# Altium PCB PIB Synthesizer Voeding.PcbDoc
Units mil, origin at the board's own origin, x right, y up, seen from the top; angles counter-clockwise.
Board outline 7800 x 2080 mil, 2 copper layers (Top Layer, Bottom Layer); 39 components, 26 nets, 116 pads, 17 vias.
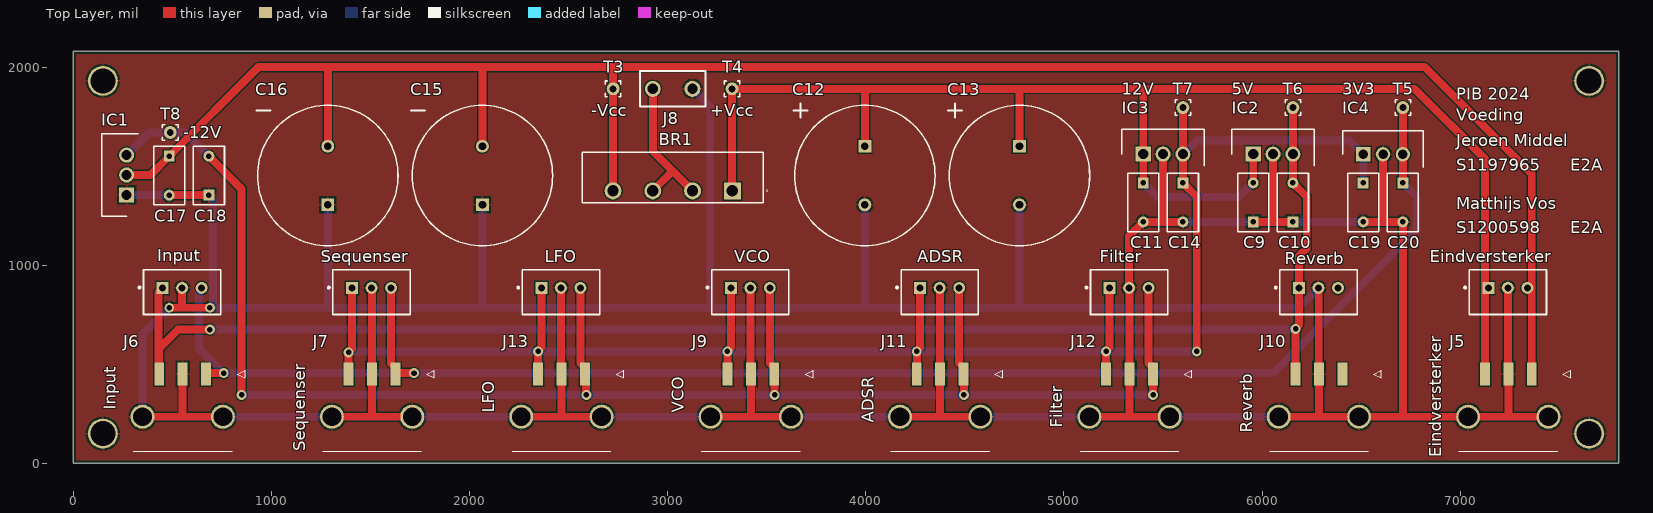
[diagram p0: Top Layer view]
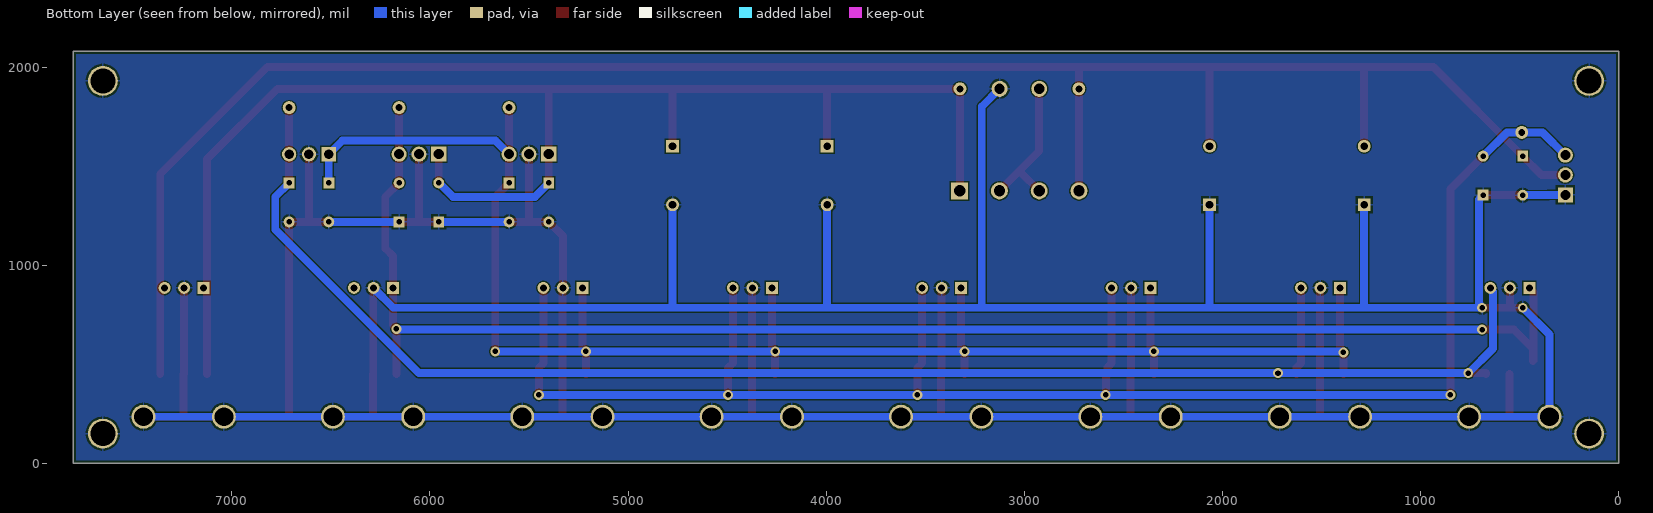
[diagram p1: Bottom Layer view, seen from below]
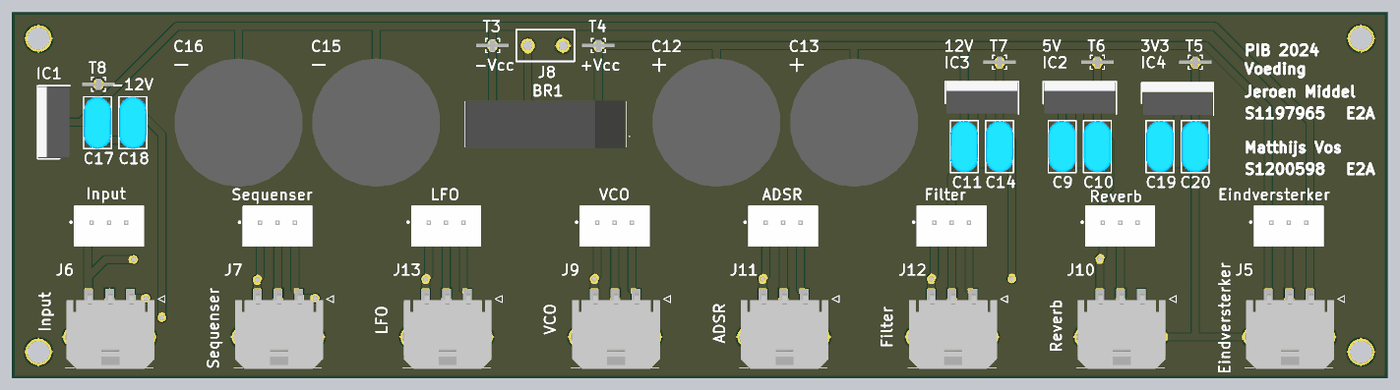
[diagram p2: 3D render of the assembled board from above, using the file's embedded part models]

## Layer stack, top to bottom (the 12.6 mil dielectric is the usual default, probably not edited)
Top Solder: solder mask 0.4, Solder Resist, Dk 3.5
Top Layer: signal copper 1.4
Dielectric 1: dielectric 12.6, FR-4, Dk 4.8
Bottom Layer: signal copper 1.4
Bottom Solder: solder mask 0.4, Solder Resist, Dk 3.5

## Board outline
0,0 7800,0 7800,2080 0,2080

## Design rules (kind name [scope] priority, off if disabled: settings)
BoardOutlineClearance "BoardOutlineClearance AISLER" [All] p1: gap=11.81 ignorepadtopadclearanceinfootprint=FALSE
Clearance "Clearance AISLER Simple" [All] p1: gap=5.91 ignorepadtopadclearanceinfootprint=FALSE except(0: Arc-Text Track-Text SMDPad-Text THPad-Text Via-Text Fill-Text Poly-Text Region-Text Text-Text Text-Hole; 7.87: Fill-Fill Fill-Poly Fill-Region Poly-Poly Poly-Region Region-Region; 9.84: Arc-Hole Track-Hole SMDPad-Hole THPad-Hole Via-Hole Fill-Hole Poly-Hole Region-Hole)
Height [All] p1: minheight=0 maxheight=3000 prefheight=500
HoleSize [All] p1: absolutevalues=TRUE maxlimit=220 minlimit=1 maxpercent=80.000 minpercent=20.000
HoleSize "HoleSize NPTH AISLER Simple" [PadIsPlated = 'False'] p2: absolutevalues=TRUE maxlimit=228.35 minlimit=11.81 maxpercent=80.000 minpercent=20.000
HoleSize "HoleSize PTH AISLER Simple" [All] p3: absolutevalues=TRUE maxlimit=222.44 minlimit=11.81 maxpercent=80.000 minpercent=20.000
HoleToHoleClearance "HoleToHoleClearance NPTH-NPTH AISLER" [PadIsPlated = 'False' vs PadIsPlated = 'False'] p2: gap=11.81 allowstackedmicrovias=FALSE // 0.25 + (0.05/2 + 0.05/2)
HoleToHoleClearance "HoleToHoleClearance NPTH-PTH AISLER" [PadIsPlated = 'False' vs PadIsPlated = 'True'] p3: gap=13.78 allowstackedmicrovias=FALSE // 0.25 + (0.05/2 + 0.15/2)
HoleToHoleClearance "HoleToHoleClearance Rest AISLER" [All] p4: gap=15.75 allowstackedmicrovias=FALSE // 0.25 + (0.15/2 + 0.15/2)
MinimumAnnularRing "MinimumAnnularRing AISLER" [IsVia] p1: minimumring=7.87
MinimumAnnularRing [All] p2: minimumring=12
MinimumSolderMaskSliver "MinimumSolderMaskSliver AISLER" [All] p2: minsoldermaskwidth=4.53 // AISLER enlarges all Solder Mask Openings by 20um by default, final Sliver is thus 0.075mm
PlaneClearance "PlaneClearance AISLER Simple" [All] p2: clearance=7.87
PolygonConnect [All] p1: connectstyle=Relief reliefconductorwidth=10 reliefentries=4 polygonreliefangle="90 Angle" airgapwidth=10
RoutingVias [All] p1: holewidth=28 width=50 viastyle="Through Hole" minholewidth=28 minwidth=50 maxholewidth=28 maxwidth=50
RoutingVias "RoutingVias AISLER Simple" [All] p2: holewidth=29.53 width=45.28 viastyle="Through Hole" minholewidth=11.81 minwidth=27.56 maxholewidth=39.37 maxwidth=55.12 // only minimum size relevant
SilkToSolderMaskClearance "SilkToSolderMaskClearance AISLER" [IsPad] p1: minsilkscreentomaskgap=5 clearancetoexposedcopper=TRUE
SolderMaskExpansion [All] p1: expansion=4 istentingtop=FALSE
Width [All] p1: maxlimit=40 minlimit=40 preferedwidth=40 minimp=50.000000 maximp=50.000000 favimp=50.000000
Width "Width AISLER Simple" [All] p2: maxlimit=59.06 minlimit=7.87 preferedwidth=19.68 // only min is relevant
27 further rules are at their usual default settings.

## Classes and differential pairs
component class "PIB Synthesizer Eindversterker": U1A U1B X1
component class "PIB Synthesizer Voeding": 5V 12V BR1 C9 C10 C12 C13 C14 C15 C16 C17 C18 C19 C20 IC1 IC4 J5 J6 J7 J9 J10 J11 J12 J13 "T3 -" "T4 +" T5 T6 T7 T8

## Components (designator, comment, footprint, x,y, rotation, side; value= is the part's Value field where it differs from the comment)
ADSR "Comment" FP-B3B-XH-A_LF_SN-MFG 4372.86,864.33 r0 top
BR1 "KBU8B-E4_51" KBU8BE451 3326.57,1375 r0 top
C9 "220nF" FP-RDE4K1-MFG 5955,1316.57 r90 top
C10 "100nF" FP-RDE4K1-MFG 6155,1316.57 r90 top
C11 "220nF" FP-RDE4K1-MFG 5400,1316.57 r270 top
C12 "4700µF" CAPPRD750W82D1800H3750 3995,1600 r270 top
C13 "4700µF" CAPPRD750W82D1800H3750 4775,1600 r270 top
C14 "100nF" FP-RDE4K1-MFG 5600,1316.57 r270 top
C15 "4700µF" CAPPRD750W82D1800H3750 2065,1304.72 r90 top
C16 "4700µF" CAPPRD750W82D1800H3750 1285,1304.72 r90 top
C17 "220nF" FP-RDE4K1-MFG 485,1451.57 r270 top
C18 "100nF" FP-RDE4K1-MFG 685,1451.57 r90 top
C19 "330uF" FP-RDE4K1-MFG 6510,1316.57 r270 top
C20 "100nF" FP-RDE4K1-MFG 6710,1316.57 r270 top
Eindversterker "Comment" FP-B3B-XH-A_LF_SN-MFG 7240,864.33 r0 top
Filter "Comment" FP-B3B-XH-A_LF_SN-MFG 5328.57,864.33 r0 top
IC1 "LM7912CT" TO254P470X1028X1955-3P 270,1355 r90 top (schematic designator U2)
IC2 "5V" TO254P470X1028X1955-3P 5955,1560 r0 top
IC3 "12V" TO254P470X1028X1955-3P 5400,1560 r0 top
IC4 "3V3" TO254P470X1016X1965-3P 6510,1560 r0 top
Input "Comment" FP-B3B-XH-A_LF_SN-MFG 550,864.33 r0 top
J5 "Eindversterker" 43650-03YY_091011 7242.24,450.35 r0 top
J6 "Input" 43650-03YY_091011 552.76,450.35 r0 top
J7 "Sequenser" 43650-03YY_091011 1508.4,450.35 r0 top
J9 "VCO" 43650-03YY_091011 3419.68,450.35 r0 top
J10 "Reverb" 43650-03YY_091011 6286.6,450.35 r0 top
J11 "ADSR" 43650-03YY_091011 4375.32,450.35 r0 top
J12 "Filter" 43650-03YY_091011 5330.96,450.35 r0 top
J13 "LFO" 43650-03YY_091011 2464.04,450.35 r0 top
LFO "Comment" FP-B3B-XH-A_LF_SN-MFG 2461.43,864.33 r0 top
Reverb "Comment" FP-B3B-XH-A_LF_SN-MFG 6284.29,864.33 r0 top
Sequenser "Comment" FP-B3B-XH-A_LF_SN-MFG 1505.71,864.33 r0 top
T3 "Testpoint -Vcc" SAMTEC_MTMM-101-X-X-S-X 2725,1890 r90 top
T4 "Testpoint +Vcc" SAMTEC_MTMM-101-X-X-S-X 3325,1890 r90 top
T5 "Testpoint +3v3" SAMTEC_MTMM-101-X-X-S-X 6710,1795 r90 top
T6 "Testpoint +5v" SAMTEC_MTMM-101-X-X-S-X 6155,1795 r90 top
T7 "Testpoint +12v" SAMTEC_MTMM-101-X-X-S-X 5600,1795 r90 top
T8 "Testpoint -12v" SAMTEC_MTMM-101-X-X-S-X 490,1670 r90 top
VCO "Comment" FP-B3B-XH-A_LF_SN-MFG 3417.14,864.33 r0 top

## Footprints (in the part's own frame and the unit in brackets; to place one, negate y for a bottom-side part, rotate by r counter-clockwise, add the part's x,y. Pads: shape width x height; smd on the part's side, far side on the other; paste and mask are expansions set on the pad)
43650-03YY_091011 [mm]
  rect 1.27x2.92 smd: 1(3,0) 2(0,0) 3(-3,0)
  round 3.062 hole 2.41: 4(5.15,-5.47) 5(-5.15,-5.47)
  silkscreen extent -6.32,-9.9 8,0.5, body extent -6.17,-10.06 6.47,0.68, height 5.71
CAPPRD750W82D1800H3750 [mm]
  rect 1.652x1.652 hole 1: 1(0,0)
  round 1.652 hole 1: 2(7.5,0)
  silkscreen extent -5.25,-9 12.75,9, body extent -5.5,-9.23 13,9.23, height 37.5
FP-B3B-XH-A_LF_SN-MFG [mm]
  rect 1.527x1.527 hole 0.9 paste-2539.97 mask+0: 1(-2.5,0.525)
  round 1.527 hole 0.9 paste-2539.97 mask+0: 2(0,0.525) 3(2.5,0.525)
  silkscreen extent -5.6,-2.88 4.95,2.88, body extent -5.05,-2.98 5.05,2.98, height 0.25
FP-RDE4K1-MFG [mm]
  rect 1.403x1.403 hole 0.7 paste-2539.97 mask+0: 1(-2.5,0)
  round 1.403 hole 0.7 paste-2539.97 mask+0: 2(2.5,0)
  silkscreen extent -3.75,-2 3.75,2, body extent -3.85,-2.1 3.85,2.1, height 0.25
KBU8BE451 [mm]
  rect 2.175x2.175 hole 1.45: 1(0,0)
  round 2.175 hole 1.45: 2(-5.1,0) 3(-10.2,0) 4(-15.3,0)
  silkscreen extent -19.25,-1.53 4.5,4.95, body extent -19.25,-1.71 3.95,5.14, height 20.51
SAMTEC_MTMM-101-X-X-S-X [mm]
  round 1.652 hole 0.89: 01(0,0)
  silkscreen extent -1,-1 1,1
TO254P470X1016X1965-3P [mm]
  rect 1.83x1.83 hole 1.22: 1(0,0)
  round 1.83 hole 1.22: 2(2.54,0) 3(5.08,0)
  silkscreen extent -2.64,-1.68 7.72,3.03, body extent -2.54,-1.61 7.62,2.96, height 21.39
TO254P470X1028X1955-3P [mm]
  rect 1.935x1.935 hole 1.29: 1(0,0)
  round 1.935 hole 1.29: 2(2.54,0) 3(5.08,0)
  silkscreen extent -2.73,-1.5 7.81,3.2, body extent -2.54,-1.43 7.62,3.14, height 19.38

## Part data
BR1: "Bridge Rectifier", Arrow Part Number=KBU8B-E4/51, Manufacturer_Name=Vishay, Mouser Part Number=625-KBU8B-E4
C9 C10 C11 C14 C17 C18 C19 C20: library part CMP-06035-043861-1, "Ceramic Capacitor 47nF ±10% 1kV X7R Radial", Case/Package=Radial, Dielectric=X7R, Max Operating Temperature=125°C, Min Operating Temperature=-55°C, Package Quantity=500, Resistor Type=Ceramic, Tolerance=10%, Voltage Rating=1kV
C12 C13 C15 C16: library part 860020581026, "Capacitor Polarised", Manufacturer_Name="Wurth Elektronik", Mouser Part Number=710-860020581026
IC1: "Undefined or Miscellaneous", Manufacturer_Name="Texas Instruments", Mouser Part Number=926-LM7912CT
IC2: library part LM7805CT, "Integrated Circuit", Manufacturer_Name="Texas Instruments", Mouser Part Number=926-LM7805CT
IC3: library part LM7812CT, "Integrated Circuit", Manufacturer_Name="Texas Instruments", Mouser Part Number=926-LM7812CT
IC4: library part UA78M33CKCSE3, "Integrated Circuit", Manufacturer_Name="Texas Instruments", Mouser Part Number=595-UA78M33CKCSE3
J5 J6 J7 J9 J10 J11 J12 J13: library part 43650-0310, "Connector", Manufacturer_Name=Molex, Mouser Part Number=538-43650-0310
T3 T4 T5 T6 T7 T8: library part MTMM-101-X-X-S-X, "Connector Header Through Hole 1 position", Package=None

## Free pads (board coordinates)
  round 150.98 hole 125.98: 4(150,150) 4(150,1930) 4(7650,150) 4(7650,1930)
  round 80.93 hole 51.18: 5(2925,1890) 6(3125,1890)

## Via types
v1: diameter 50, hole 28, Top Layer to Bottom Layer, 17 vias

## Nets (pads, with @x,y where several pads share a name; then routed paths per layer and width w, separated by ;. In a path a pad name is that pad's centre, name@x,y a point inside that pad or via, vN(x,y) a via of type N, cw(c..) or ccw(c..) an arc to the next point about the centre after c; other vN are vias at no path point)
+3v3: C20.1 IC4.3 Input.3 J6.1 J7.1 Sequenser.3 T5.01 | length 8078.2
  Top Layer w40: J6.1 J6.1@671.04,450.18 ; J6.1@671.04,455.18 v1@759.82,455.18 ; v1@759.82,450.18 v1@760,450 ; Sequenser.3 1604.14,505.2 1626.51,482.83 J7.1 ; J7.1@1626.68,455.18 v1@1719.82,455.18 ; v1@1719.82,450.18 v1@1720,450 ; C20.1 IC4.3 T5.01
  Bottom Layer w40: Input.3 648.43,880.91 635,867.48 635,580 v1(760,455) v1(1720,455) 6055,455 6780,1180 6780,1345 C20.1
+5: C10.2 IC2.3 Input.1 J6.3 J10.3 Reverb.1 T6.01 | length 7617.4
  Top Layer w40: Input.1 430,863.43 430,579.65 430,519.65 434.65,515 434.65,579.65 530,675 v1(690,675) ; T6.01 IC2.3 C10.2 6225,1345 6225,1085 6185.86,1045.86 Reverb.1 6185.86,698.57 6168.49,681.2 v1(6168.49,678.49) J10.3
  Bottom Layer w40: v1(690,675) v1@6170,675
+12: ADSR.1 C14.1 C19.1 Filter.1 IC3.3 IC4.1 J7.3 J9.3 J11.3 J12.3 J13.3 LFO.1 Sequenser.1 T7.01 VCO.1 | length 8859.3
  Top Layer w40: v1(1390,560) 1390,562.71 1407.29,579.99 Sequenser.1 ; J7.3 v1@1390.29,560 ; J13.3 v1(2345.93,565) 2345.93,567.71 2363,584.78 LFO.1 ; J9.3 v1(3301.57,565) 3301.57,567.71 3318.72,584.85 VCO.1 ; J11.3 v1(4257.21,565) 4257.21,567.71 4274.43,584.93 ADSR.1 ; J12.3 v1(5212.85,565) 5212.85,567.71 5230.15,585 Filter.1 ; T7.01 IC3.3 C14.1 5670,1345 v1(5670,565)
  Bottom Layer w40: v1@1390,565 v1(2345.93,565) v1(3301.57,565) v1(4257.21,565) v1(5212.85,565) v1(5670,565) ; IC3.3 5668.09,1628.09 6441.91,1628.09 IC4.1 C19.1
-12: ADSR.3 C18.2 Filter.3 IC1.3 J9.1 J11.1 J12.1 J13.1 LFO.3 T8.01 VCO.3 | length 8588.3
  Top Layer w40: C18.2 850,1385 v1(850,345) ; LFO.3 2559.85,505.13 2581.07,483.91 J13.1@2581.07,449.28 ; J13.1 2587.15,445.35 2587.15,350.56 2590,347.71 v1(2590,345) ; VCO.3 3515.57,505.06 3540,480.62 v1(3540,345) ; ADSR.3 4471.28,504.98 4495,481.27 v1(4495,345) ; Filter.3 5427,504.91 5450,481.91 v1(5450,345)
  Bottom Layer w40: IC1.3 385,1670 T8.01 565,1670 C18.2 ; v1(850,345) v1(2590,345) v1(3540,345) v1(4495,345) v1(5450,345)
-VCC: BR1.4 C15.2 C16.2 C17.1 Eindversterker.3 IC1.2 J5.1 T3.01 | length 9973.4
  Top Layer w40: IC1.2 390,1455 C17.1 935,2000 1285,2000 ; C16.2 1285,2000 ; C15.2 2065,2000 ; BR1.4@2724.9,1375.69 T3.01@2724.9,1889.9 ; T3.01 2725,2000 ; J5.1 7360.35,1459.65 6820,2000 2725,2000 ; 1285,2000 2065,2000 ; 2065,2000 2725,2000
GND: ADSR.2 C9.1 C10.1 C11.2 C12.2 C13.2 C14.2 C15.1 C16.1 C17.2 C18.1 C19.2 C20.2 Eindversterker.2 Filter.2 IC1.1 IC2.2 IC3.2 IC4.2 Input.2 J5.2 J5.4 J5.5 J6.2 J6.4 J6.5 J7.2 J7.4 J7.5 J9.2 J9.4 J9.5 J10.2 J10.4 J10.5 J11.2 J11.4 J11.5 J12.2 J12.4 J12.5 J13.2 J13.4 J13.5 LFO.2 pad.4 pad.6 Reverb.2 Sequenser.2 VCO.2 | length 30114.3
  Top Layer w40: J6.5 552.76,235 ; v1(485,785) 550,785 ; C17.2 C18.1 ; Input.2 550,785 ; J6.2 552.76,235 ; v1(690,785) 550,785 ; J6.4 552.76,235 ; J7.5 1508.4,235 ; Sequenser.2 1507.06,883.66 1507.06,451.7 J7.2 1508.4,235 ; J7.4 1508.4,235 ; J13.5 2464.04,235 ; LFO.2 2462.73,883.7 2462.73,451.66 J13.2 2464.04,235 ; J13.4 2464.04,235 ; J9.5 3419.68,235 ; VCO.2 3418.41,883.73 3418.41,451.62 J9.2 3419.68,235 ; J9.4 3419.68,235 ; J11.5 4375.32,235 ; ADSR.2 4374.09,883.77 4374.09,451.59 J11.2 4375.32,235 ; J11.4 4375.32,235 ; J12.5 5330.96,235 ; IC3.2 5500,1218.15 ; J12.4 5330.96,235 ; C14.2 5500,1218.15 ; C9.1 6055,1218.15 ; IC2.2 6055,1218.15 ; J10.5 6286.6,235 ; C10.1 6055,1218.15 ; Reverb.2 6285.44,883.84 6285.44,451.51 J10.2 6286.6,235 ; C19.2 6610,1218.15 ; IC4.2 6610,1218.15 ; Eindversterker.2 7241.12,883.88 7241.12,451.48 J5.2 7242.24,235 ; J5.4 7242.24,235 ; 5330.96,235 J12.2 5329.77,451.55 5329.77,883.8 Filter.2 5328.57,1146.72 C11.2 5500,1218.15 ; 6286.6,235 J10.4 6710,235 ; 6610,1218.15 C20.2 6710,235 ; 6710,235 J5.5 7242.24,235
  Bottom Layer w40: IC1.1 355,1355 356.85,1353.15 C17.2 ; v1(485,785) 350,650 J6.5 J6.4 J7.5 J7.4 J13.5 J13.4 J9.5 J9.4 J11.5 J11.4 J12.5 J12.4 J10.5 J10.4 J5.5 J5.4 ; C18.1 705.98,1332.17 705.98,803.69 690,787.71 v1(690,785) 1285,785 ; C16.1 1285,785 ; C15.1 2065,790 2060,785 ; pad.6 3215,1800 3215,790 3210,785 ; C12.2 3995,785 ; C13.2 4775,785 ; C14.2 C9.1 ; C10.1 C19.2 ; Reverb.2 6184.29,785 4775,785 ; 1285,785 2060,785 ; 2060,785 3210,785 ; 3210,785 3995,785 ; 3995,785 4775,785
NetBR1_2: BR1.2 BR1.3 pad.5 | length 740.1
  Top Layer w40: BR1.3 3025.39,1475.39 ; pad.5 2925,1575.79 3025.39,1475.39 ; BR1.2 3025.39,1475.39
NetC4_1: 
NetC4_2: 
NetC6_1: 
NetJ2_2: 
NetJ4_3: 
NetJ8_1: 
NetQ1_G: 
NetQ1_S: 
NetQ2_B: 
NetQ2_E: 
NetQ3_B: 
NetQ3_C: 
NetQ4_S: 
NetR3_1: 
NetR8_2: 
NetR11_1: 
NetU1A_1: 
NetU1B_2: 
VCC: BR1.1 C9.2 C11.1 C12.1 C13.1 Eindversterker.1 IC2.1 IC3.1 J5.3 T4.01 | length 7361.5
  Top Layer w40: BR1.1@3325,1376.57 T4.01 3990,1890 ; C12.1 3995,1885 3990,1890 ; C13.1 4775,1885 4770,1890 ; C11.1 IC3.1 5400,1890 ; C9.2@5953.04,1415 C9.2 IC2.1 ; J5.3 7124.13,1535.16 6769.29,1890 5400,1890 ; 3990,1890 4770,1890 ; 4770,1890 5400,1890
  Bottom Layer w40: C11.1 5470,1345 5883.04,1345 C9.2@5953.04,1415
pads on no net: J10.1 Reverb.3

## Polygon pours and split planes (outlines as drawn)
GND on Bottom Layer "GND_L02_P000" (solid, pour order 0): 15,15 15,2065 7785,2065 7785,15
GND on Top Layer "GND_L01_P001" (solid, pour order 1): 15.52,14.37 15.52,2064.37 7785.52,2064.37 7785.52,14.37

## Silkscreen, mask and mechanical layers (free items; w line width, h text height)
Top Overlay:
  lines w10: 925,1780 995,1780 ; 1705,1780 1775,1780 ; 3635,1780 3705,1780 ; 3670,1745 3670,1815 ; 4415,1780 4485,1780 ; 4450,1745 4450,1815 ; 2860,1800 3190,1800 3190,1980 2860,1980 2860,1800
  text "PIB 2024" at 6980,1835 h60
  text "-Vcc" at 2615,1751 h60
  text "+Vcc" at 3215,1751 h60
  text "Voeding" at 6980,1729.99 h60
  text "J8" at 2975,1710 h60
  text "-12V" at 555,1640 h60
  text "Jeroen Middel" at 6980,1600 h60
  text "S1197965" at 6980,1476.66 h60
  text "E2A" at 7555,1476.66 h60
  text "Matthijs Vos" at 6980,1283.34 h60
  text "S1200598" at 6980,1160 h60
  text "E2A" at 7555,1160 h60
Mechanical 1:
  the board outline again, w10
